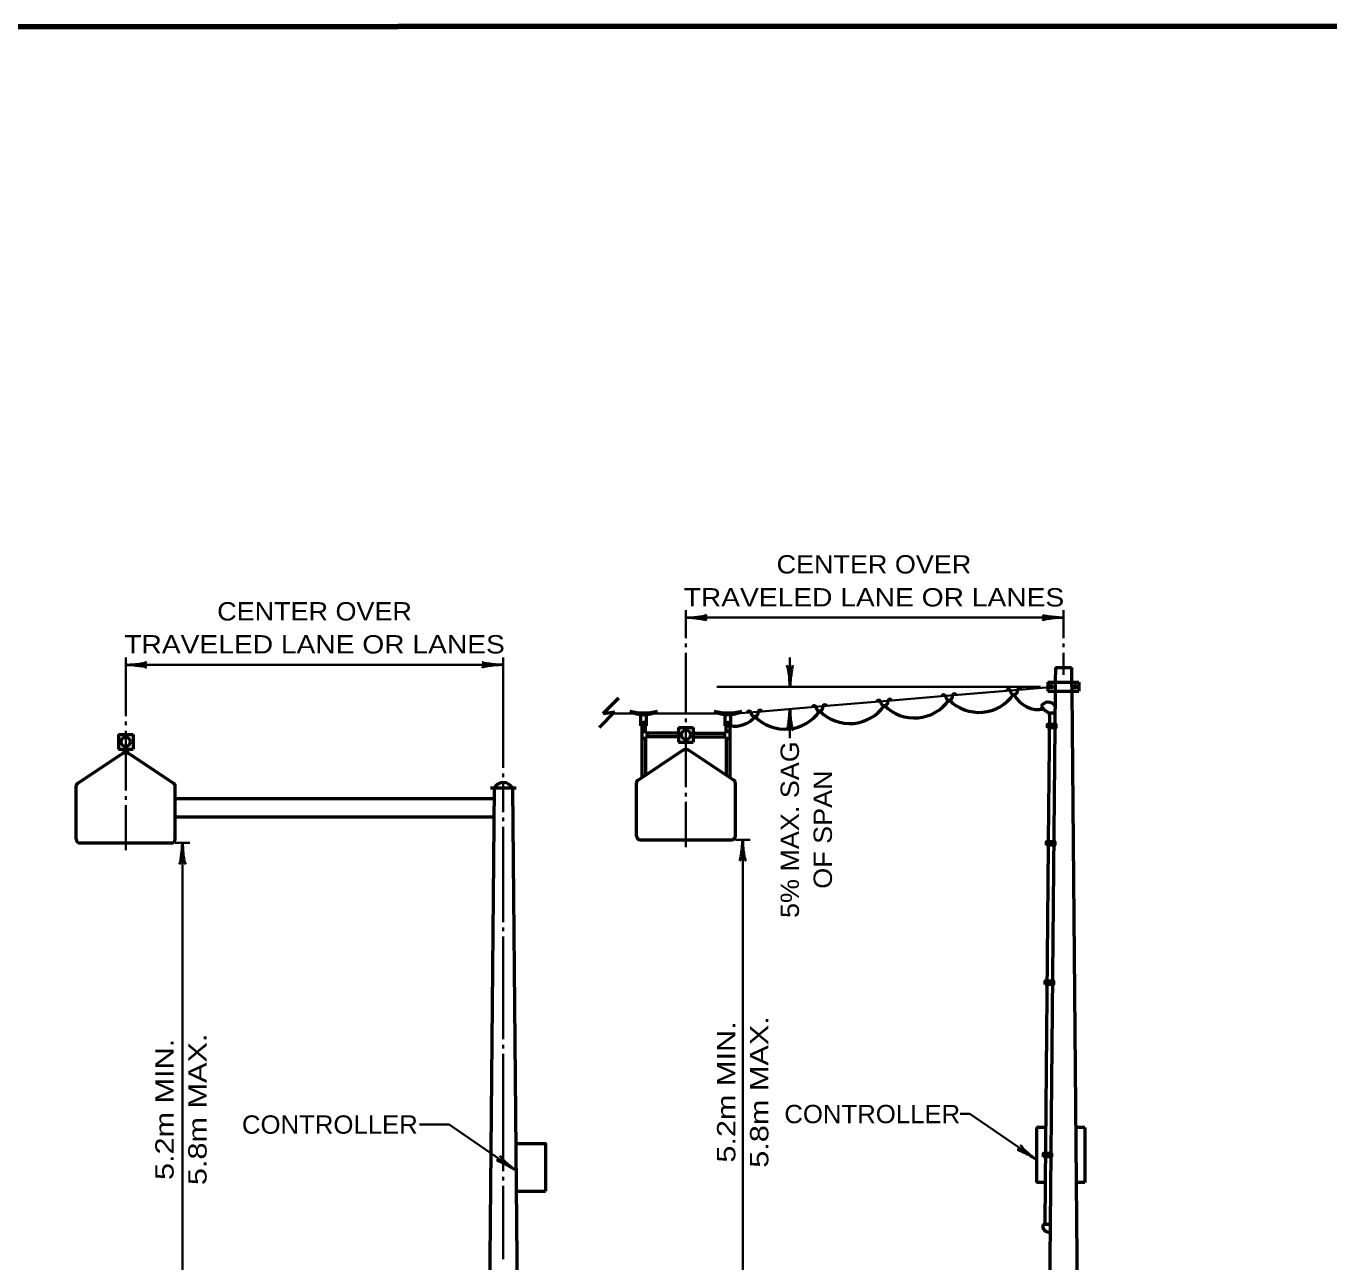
# Model space of a CAD drawing. Extents: x -35 to 821, y -10 to 534.
# Drawn here: x 357.6 to 571, y 325 to 527.4 of the extents above; entities that cross this region are included whole.
import ezdxf
from ezdxf.enums import TextEntityAlignment as Align

# ---------------------------------------------------------------- set-up
doc = ezdxf.new("R2010")
doc.units = 0
doc.header["$LTSCALE"] = 1.2
doc.layers.add('1', color=7, linetype='Continuous', lineweight=35)

msp = doc.modelspace()

# ---------------------------------------------------------------- hatches: boundary and pattern name
at = {"layer": '1'}
for points in [[(525.717, 419.199, 1), (525.329, 419.199, 1)], [(529.608, 419.199, 1), (529.219, 419.199, 1)], [(458.917, 413.259, 1), (458.617, 413.259, 1)], [(472.718, 413.256, 1), (472.418, 413.256, 1)]]:
    msp.add_hatch(color=256, dxfattribs=at).paths.add_polyline_path(points)

# ---------------------------------------------------------------- linework, layer by layer
for p, q in [((465.669, 431.705), (465.669, 427.146)), ((527.486, 427.146), (527.486, 431.705)), ((465.669, 430.505), (527.486, 430.505)), ((465.669, 426.246), (465.669, 425.646)), ((465.669, 424.746), (465.669, 414.905)), ((527.486, 425.646), (527.486, 426.246)), ((527.486, 421.146), (527.486, 424.746)), ((373.951, 423.976), (373.951, 414.376)), ((373.951, 422.776), (435.768, 422.776)), ((435.768, 405.91), (435.768, 423.976)), ((482.713, 419.196), (482.713, 423.996)), ((470.713, 419.196), (523.741, 419.196)), ((507.557, 417.646), (518.174, 418.541)), ((518.174, 418.541), (525.337, 419.144)), ((478.105, 415.163), (488.72, 416.058)), ((488.72, 416.058), (499.338, 416.953)), ((499.338, 416.953), (507.56, 417.646)), ((457.421, 414.811), (453.798, 414.811)), ((471.221, 414.811), (460.117, 414.811)), ((465.669, 414.005), (465.669, 413.405)), ((473.917, 414.81), (478.105, 415.163)), ((482.713, 410.752), (482.713, 415.552)), ((373.951, 413.476), (373.951, 412.876)), ((373.951, 408.376), (373.951, 402.197)), ((465.669, 408.905), (465.669, 402.726)), ((435.768, 404.41), (435.768, 405.01)), ((435.768, 403.51), (435.768, 398.679)), ((373.951, 401.297), (373.951, 400.697)), ((465.669, 401.826), (465.669, 401.226)), ((373.951, 399.797), (373.951, 393.619)), ((465.669, 400.326), (465.669, 394.147)), ((435.768, 397.179), (435.768, 397.779)), ((435.768, 396.279), (435.768, 380.679)), ((373.951, 393.619), (373.951, 392.418)), ((382.051, 393.619), (384.451, 393.619)), ((383.251, 393.619), (383.251, 302.418)), ((465.669, 394.147), (465.669, 392.947)), ((473.769, 394.147), (476.169, 394.147)), ((474.969, 394.147), (474.969, 302.947)), ((435.768, 379.179), (435.768, 379.779)), ((435.768, 378.279), (435.768, 361.479)), ((435.768, 359.979), (435.768, 360.579)), ((435.768, 359.079), (435.768, 339.879)), ((435.768, 338.379), (435.768, 338.979)), ((435.768, 337.479), (435.768, 325.479))]:
    msp.add_line(p, q, dxfattribs=at)
at = {"layer": '1', "lineweight": 53}
for p, q in [((526.164, 422.346), (526.141, 419.946)), ((526.164, 422.346), (528.808, 422.346)), ((528.808, 422.346), (528.83, 419.946)), ((524.941, 419.946), (530.03, 419.946)), ((524.941, 419.946), (524.941, 418.446)), ((524.941, 418.446), (530.03, 418.446)), ((526.127, 418.446), (525.086, 305.947)), ((526.139, 419.646), (526.13, 418.746)), ((528.833, 419.646), (528.841, 418.746)), ((528.844, 418.446), (529.886, 305.947)), ((530.03, 419.946), (530.03, 418.446)), ((452.14, 414.825), (454.686, 417.37)), ((524.667, 415.156), (523.818, 416.005)), ((451.501, 412.513), (454.046, 415.059)), ((452.14, 414.825), (454.046, 415.059)), ((458.319, 412.805), (458.319, 414.605)), ((459.219, 412.805), (459.219, 414.605)), ((472.119, 412.805), (472.119, 414.605)), ((473.019, 412.805), (473.019, 414.605)), ((526.094, 414.846), (524.894, 414.846)), ((525.194, 414.846), (524.999, 393.855)), ((458.319, 412.805), (459.219, 412.805)), ((458.469, 412.805), (458.469, 404.347)), ((459.069, 411.905), (458.469, 411.905)), ((459.069, 411.605), (459.069, 412.805)), ((464.469, 412.505), (466.869, 412.505)), ((464.469, 412.505), (464.469, 410.105)), ((466.869, 412.505), (466.869, 410.105)), ((472.119, 412.805), (473.019, 412.805)), ((472.269, 411.605), (472.269, 412.805)), ((472.269, 411.905), (472.869, 411.905)), ((472.869, 412.805), (472.869, 404.347)), ((372.751, 411.376), (375.151, 411.376)), ((372.751, 411.376), (372.751, 408.976)), ((375.151, 411.376), (375.151, 408.976)), ((459.069, 410.705), (458.469, 410.705)), ((464.469, 411.605), (459.069, 411.605)), ((464.469, 411.005), (459.069, 411.005)), ((459.069, 411.005), (459.069, 404.747)), ((459.369, 411.605), (459.369, 411.005)), ((464.469, 410.105), (466.869, 410.105)), ((466.869, 411.605), (472.269, 411.605)), ((466.869, 411.005), (472.269, 411.005)), ((471.969, 411.605), (471.969, 411.005)), ((472.269, 411.005), (472.269, 404.747)), ((472.269, 410.705), (472.869, 410.705)), ((366.118, 403.397), (373.285, 408.175)), ((372.751, 408.976), (375.151, 408.976)), ((373.651, 408.976), (373.651, 408.338)), ((374.251, 408.976), (374.251, 408.338)), ((374.616, 408.175), (381.784, 403.397)), ((457.837, 403.925), (465.004, 408.703)), ((466.335, 408.703), (473.502, 403.925)), ((457.569, 394.747), (457.569, 403.426)), ((473.769, 394.747), (473.769, 403.426)), ((365.851, 394.219), (365.851, 402.897)), ((382.051, 394.219), (382.051, 402.897)), ((434.268, 402.619), (433.368, 305.418)), ((433.668, 402.619), (437.868, 402.619)), ((437.268, 402.619), (438.168, 305.418)), ((434.251, 400.819), (382.051, 400.819)), ((434.223, 397.819), (382.051, 397.819)), ((366.451, 393.619), (381.451, 393.619)), ((458.169, 394.147), (473.169, 394.147)), ((524.994, 393.247), (524.483, 338.057)), ((523.066, 347.05), (523.066, 338.057)), ((524.566, 347.05), (523.066, 347.05)), ((531.005, 347.05), (529.505, 347.05)), ((531.005, 347.05), (531.005, 338.057)), ((524.483, 338.057), (523.066, 338.057)), ((524.483, 338.057), (524.419, 331.146)), ((531.005, 338.057), (529.589, 338.057)), ((437.879, 336.617), (442.679, 336.617)), ((525.319, 331.146), (524.119, 331.146))]:
    msp.add_line(p, q, dxfattribs=at)
at = {"layer": '1', "lineweight": 158}
msp.add_lwpolyline([(814.384, 527.35), (22.684, 527.25), (22.784, 1.25)], dxfattribs=at)
at = {"layer": '1'}
for points in [[(373.951, 411.976), (373.951, 408.976), (373.951, 408.376)], [(465.669, 412.505), (465.669, 409.505), (465.669, 408.905)], [(523.057, 341.798), (512.185, 349.252), (510.588, 349.252)], [(437.789, 340.059), (426.917, 347.513), (422.053, 347.513)]]:
    msp.add_lwpolyline(points, dxfattribs=at)
at = {"layer": '1', "lineweight": 53}
for points in [[(524.894, 412.446), (524.894, 413.046), (526.244, 413.046), (526.244, 412.446)], [(524.722, 393.255), (524.722, 393.855), (526.072, 393.855), (526.072, 393.255)], [(524.493, 370.448), (524.493, 371.048), (525.843, 371.048), (525.843, 370.448)], [(524.202, 342.25), (524.202, 342.85), (525.552, 342.85), (525.552, 342.25)]]:
    msp.add_lwpolyline(points, close=True, dxfattribs=at)
msp.add_lwpolyline([(437.807, 344.417), (442.679, 344.417), (442.679, 336.617)], dxfattribs=at)
for centre, radius in [((525.523, 419.199), 0.194), ((529.413, 419.199), 0.194), ((458.767, 413.259), 0.15), ((465.683, 411.317), 0.75), ((472.568, 413.256), 0.15), ((373.952, 410.175), 0.75)]:
    msp.add_circle(centre, radius, dxfattribs=at)
for centre, radius, start, end in [((518.483, 418.455), 0.32, 25.5313, 164.45861), ((520.276, 418.612), 0.32, 24.08975, 164.4687), ((486.634, 415.77), 0.32, 25.5313, 164.45861), ((492.496, 420.082), 6.917, 224.78783, 325.11132), ((488.427, 415.927), 0.32, 24.08975, 164.4687), ((497.252, 416.665), 0.32, 25.5313, 164.45861), ((503.079, 420.999), 6.917, 224.78783, 325.11132), ((499.045, 416.822), 0.32, 24.08975, 164.4687), ((507.866, 417.56), 0.32, 25.5313, 164.45861), ((513.662, 421.915), 6.917, 224.78783, 325.11132), ((509.659, 417.717), 0.32, 24.08975, 164.4687), ((523.468, 419.994), 4.547, 207.50003, 280.53329), ((524.973, 415.293), 1.357, 32.91213, 148.34152), ((458.769, 419.124), 4.519, 240.13717, 299.86284), ((458.769, 423.492), 8.588, 254.81071, 285.18929), ((472.569, 419.124), 4.519, 240.13717, 299.86284), ((472.569, 423.492), 8.588, 254.81071, 285.18929), ((473.601, 417.259), 4.514, 260.66909, 318.91993), ((476.019, 414.876), 0.32, 25.5313, 164.45861), ((481.913, 419.166), 6.917, 224.78783, 325.11132), ((477.812, 415.033), 0.32, 24.08975, 164.4687), ((524.656, 414.91), 0.246, 344.97633, 87.57779), ((373.951, 407.176), 1.2, 56.30808, 123.69007), ((465.669, 407.705), 1.2, 56.30808, 123.69007), ((366.451, 402.897), 0.6, 123.69239, 180), ((381.451, 402.897), 0.6, 0, 56.30661), ((435.767, 401.803), 1.707, 28.52934, 151.47066), ((458.169, 403.426), 0.6, 123.69239, 180), ((473.169, 403.426), 0.6, 0, 56.30661), ((458.169, 394.747), 0.6, 180, 270), ((473.169, 394.747), 0.6, 270, 0), ((366.451, 394.219), 0.6, 180, 270), ((381.451, 394.219), 0.6, 270, 0), ((525.074, 330.903), 0.986, 165.76102, 283.71131)]:
    msp.add_arc(centre, radius, start, end, dxfattribs=at)
at = {"layer": '1', "lineweight": 40}
for centre, major_axis, ratio, start_param, end_param in [((466.979, 430.836), (-2.143, -0.187), 0.122415, 0.8963533, 3.1415927), ((526.141, 430.759), (2.108, -0.211), 0.07063, 3.1407148, 5.41811), ((467.014, 430.251), (-2.108, 0.211), 0.07063, 3.1407148, 5.41811), ((526.177, 430.173), (2.143, 0.187), 0.122415, 0.8963533, 3.1415927), ((375.295, 422.522), (-2.108, 0.211), 0.07063, 3.1407148, 5.41811), ((375.295, 422.522), (-2.108, 0.211), 0.07063, 3.1407148, 5.41811), ((375.26, 423.108), (-2.143, -0.187), 0.122415, 0.8963533, 3.1415927), ((375.26, 423.108), (-2.143, -0.187), 0.122415, 0.8963533, 3.1415927), ((434.458, 422.445), (2.143, 0.187), 0.122415, 0.8963533, 3.1415927), ((434.423, 423.03), (2.108, -0.211), 0.07063, 3.1407148, 5.41811), ((482.381, 420.506), (0.187, -2.143), 0.122415, 0.8963533, 3.1415927), ((482.381, 420.506), (0.187, -2.143), 0.122415, 0.8963533, 3.1415927), ((482.967, 420.541), (-0.211, -2.108), 0.07063, 3.1407148, 5.41811), ((482.967, 420.541), (-0.211, -2.108), 0.07063, 3.1407148, 5.41811), ((482.459, 414.207), (0.211, 2.108), 0.07063, 3.1407148, 5.41811), ((482.459, 414.207), (0.211, 2.108), 0.07063, 3.1407148, 5.41811), ((483.044, 414.242), (-0.187, 2.143), 0.122415, 0.8963533, 3.1415927), ((483.044, 414.242), (-0.187, 2.143), 0.122415, 0.8963533, 3.1415927), ((382.997, 392.274), (0.211, 2.108), 0.07063, 3.1407148, 5.41811), ((383.582, 392.309), (-0.187, 2.143), 0.122415, 0.8963533, 3.1415927), ((474.715, 392.802), (0.211, 2.108), 0.07063, 3.1407148, 5.41811), ((475.301, 392.838), (-0.187, 2.143), 0.122415, 0.8963533, 3.1415927), ((522.15, 342.81), (1.661, -1.366), 0.122415, 3.1415927, 5.386832), ((436.536, 340.61), (-1.858, 1.018), 0.07063, 4.006668, 6.2840632), ((436.536, 340.61), (-1.858, 1.018), 0.07063, 4.006668, 6.2840632), ((436.896, 341.073), (1.661, -1.366), 0.122415, 3.1415927, 5.386832), ((436.896, 341.073), (1.661, -1.366), 0.122415, 3.1415927, 5.386832), ((521.79, 342.347), (-1.858, 1.018), 0.07063, 4.006668, 6.2840632)]:
    msp.add_ellipse(centre, major_axis=major_axis, ratio=ratio, start_param=start_param, end_param=end_param, dxfattribs=at)
at = {"layer": '1', "lineweight": 53}
for centre in [(519.369, 418.645), (487.521, 415.961), (498.139, 416.856), (508.753, 417.75), (476.906, 415.066)]:
    msp.add_ellipse(centre, major_axis=(0.066, -0.751), ratio=0.795507, start_param=4.712389, end_param=7.8539816, dxfattribs=at)

# ---------------------------------------------------------------- texts
at = {"layer": '1'}
for s, width, p in [('CENTER OVER', 1.1, (496.462, 437.731)), ('TRAVELED LANE OR LANES', 1.15, (496.462, 432.331)), ('CENTER OVER', 1.1, (404.874, 430.039)), ('TRAVELED LANE OR LANES', 1.15, (404.874, 424.639))]:
    msp.add_text(s, height=3, dxfattribs=dict(at, width=width)).set_placement(p, align=Align.CENTER)
for s, width, p in [('5% MAX. SAG', 1.1, (484.183, 395.803)), ('OF SPAN', 1.1, (489.583, 395.803)), ('5.8m MAX.', 1.25, (479.173, 352.85)), ('5.2m MIN.', 1.25, (473.773, 352.85)), ('5.2m MIN.', 1.25, (381.799, 350.008)), ('5.8m MAX.', 1.25, (387.199, 350.008))]:
    msp.add_text(s, height=3, rotation=90, dxfattribs=dict(at, width=width)).set_placement(p, align=Align.CENTER)
at = {"layer": '1', "width": 1.05}
for p in [(481.788, 347.743), (392.986, 346.021)]:
    msp.add_text('CONTROLLER', height=3, dxfattribs=at).set_placement(p)

doc.saveas('drawing.dxf')
